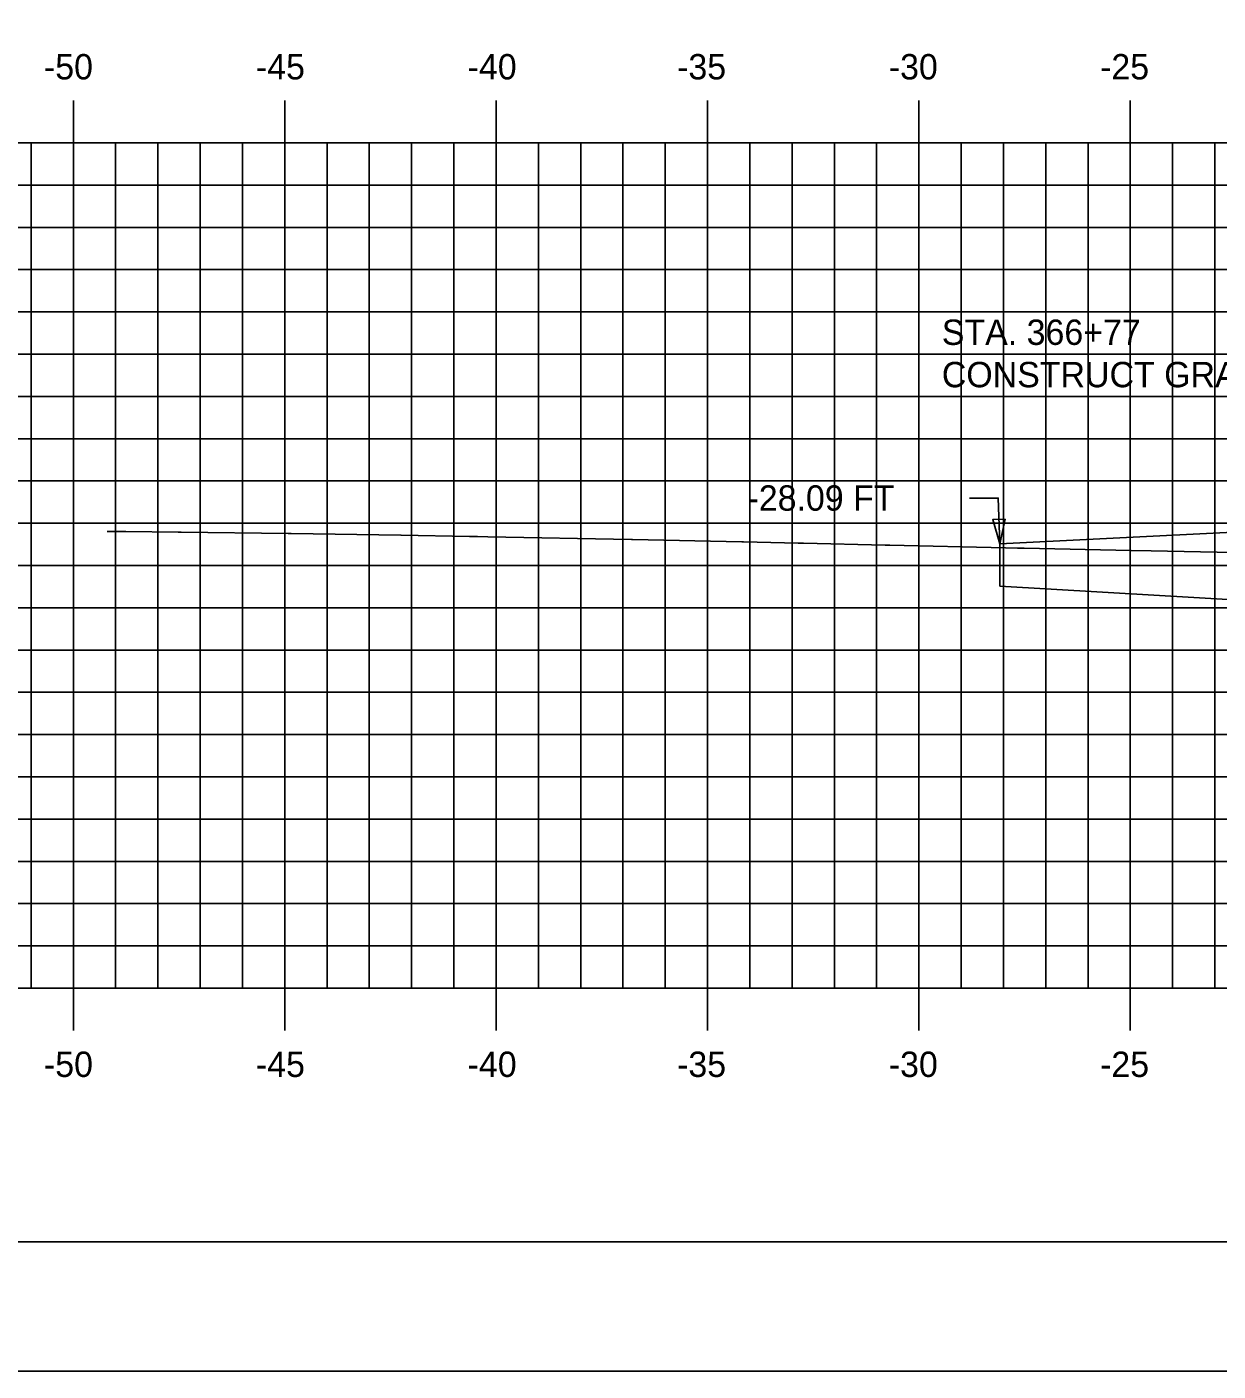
# Model space of a CAD drawing. Extents: x 1147633 to 1147803, y 608981 to 609091.
# Drawn here: x 1147665.35 to 1147693.53, y 608981.28 to 609013.08 of the extents above; entities that cross this region are included whole.
import ezdxf

# ---------------------------------------------------------------- set-up
doc = ezdxf.new("R2010")
doc.units = 0
for name, color, linetype in [('ANNOTATION', 7, 'Continuous'), ('BORDER', 7, 'Continuous'), ('D_Roadway_SubGrade', 7, 'Continuous'), ('D_Text_Standard', 7, 'Continuous'), ('H_V ANNOTATION', 7, 'Continuous'), ('MAJOR', 7, 'Continuous'), ('MINOR', 7, 'Continuous'), ('PLOT BOUNDARY', 7, 'Continuous'), ('S_Roadway_Centerline', 7, 'Continuous')]:
    doc.layers.add(name, color=color, linetype=linetype)

msp = doc.modelspace()

# ---------------------------------------------------------------- linework, layer by layer
msp.add_lwpolyline([(1147688.367, 609000.844), (1147688.37, 609000.845), (1147701.454, 609001.499), (1147701.455, 609001.499), (1147705.454, 609001.659), (1147705.457, 609001.659), (1147716.454, 609001.879), (1147716.457, 609001.879), (1147727.454, 609001.659), (1147727.455, 609001.659), (1147731.454, 609001.499), (1147731.456, 609001.498), (1147739.178, 608998.924), (1147742.178, 608997.924), (1147742.807, 608998.239), (1147744.057, 608998.789), (1147745.307, 608999.188), (1147746.557, 608999.438), (1147747.807, 608999.537)])
at = {"layer": 'BORDER'}
msp.add_lwpolyline([(1147641.454, 608984.335), (1147801.454, 608984.335), (1147801.454, 609089.335), (1147641.454, 609089.335)], close=True, dxfattribs=at)
at = {"layer": 'D_Roadway_SubGrade'}
msp.add_lwpolyline([(1147688.367, 608999.844), (1147701.454, 608999.079), (1147705.454, 608999.159), (1147705.454, 609001.242), (1147705.454, 609001.409), (1147701.454, 609001.249), (1147701.454, 609001.499), (1147688.367, 609000.844)], close=True, dxfattribs=at)
at = {"layer": 'D_Text_Standard'}
msp.add_lwpolyline([(1147688.367, 609000.844), (1147688.331, 609001.932), (1147687.651, 609001.932)], dxfattribs=at)
msp.add_lwpolyline([(1147688.367, 609000.844), (1147688.202, 609001.421), (1147688.493, 609001.431)], close=True, dxfattribs=at)
at = {"layer": 'MAJOR'}
for p, q in [((1147666.454, 609011.337), (1147666.454, 609010.335)), ((1147671.454, 609011.337), (1147671.454, 609010.335)), ((1147676.454, 609011.337), (1147676.454, 609010.335)), ((1147681.454, 609011.337), (1147681.454, 609010.335)), ((1147686.454, 609011.337), (1147686.454, 609010.335)), ((1147691.454, 609011.337), (1147691.454, 609010.335)), ((1147646.454, 609010.335), (1147786.454, 609010.335)), ((1147646.454, 609010.335), (1147786.454, 609010.335)), ((1147666.454, 608990.335), (1147666.454, 609010.335)), ((1147671.454, 608990.335), (1147671.454, 609010.335)), ((1147676.454, 608990.335), (1147676.454, 609010.335)), ((1147681.454, 608990.335), (1147681.454, 609010.335)), ((1147686.454, 608990.335), (1147686.454, 609010.335)), ((1147691.454, 608990.335), (1147691.454, 609010.335)), ((1147646.454, 609005.335), (1147786.454, 609005.335)), ((1147646.454, 609000.335), (1147786.454, 609000.335)), ((1147646.454, 608995.335), (1147786.454, 608995.335)), ((1147646.454, 608990.335), (1147786.454, 608990.335)), ((1147646.454, 608990.335), (1147786.454, 608990.335)), ((1147666.454, 608989.333), (1147666.454, 608990.335)), ((1147671.454, 608989.333), (1147671.454, 608990.335)), ((1147676.454, 608989.333), (1147676.454, 608990.335)), ((1147681.454, 608989.333), (1147681.454, 608990.335)), ((1147686.454, 608989.333), (1147686.454, 608990.335)), ((1147691.454, 608989.333), (1147691.454, 608990.335))]:
    msp.add_line(p, q, dxfattribs=at)
at = {"layer": 'MINOR'}
for p, q in [((1147665.454, 608990.335), (1147665.454, 609010.335)), ((1147667.454, 608990.335), (1147667.454, 609010.335)), ((1147668.454, 608990.335), (1147668.454, 609010.335)), ((1147669.454, 608990.335), (1147669.454, 609010.335)), ((1147670.454, 608990.335), (1147670.454, 609010.335)), ((1147672.454, 608990.335), (1147672.454, 609010.335)), ((1147673.454, 608990.335), (1147673.454, 609010.335)), ((1147674.454, 608990.335), (1147674.454, 609010.335)), ((1147675.454, 608990.335), (1147675.454, 609010.335)), ((1147677.454, 608990.335), (1147677.454, 609010.335)), ((1147678.454, 608990.335), (1147678.454, 609010.335)), ((1147679.454, 608990.335), (1147679.454, 609010.335)), ((1147680.454, 608990.335), (1147680.454, 609010.335)), ((1147682.454, 608990.335), (1147682.454, 609010.335)), ((1147683.454, 608990.335), (1147683.454, 609010.335)), ((1147684.454, 608990.335), (1147684.454, 609010.335)), ((1147685.454, 608990.335), (1147685.454, 609010.335)), ((1147687.454, 608990.335), (1147687.454, 609010.335)), ((1147688.454, 608990.335), (1147688.454, 609010.335)), ((1147689.454, 608990.335), (1147689.454, 609010.335)), ((1147690.454, 608990.335), (1147690.454, 609010.335)), ((1147692.454, 608990.335), (1147692.454, 609010.335)), ((1147693.454, 608990.335), (1147693.454, 609010.335)), ((1147646.454, 609009.335), (1147786.454, 609009.335)), ((1147646.454, 609008.335), (1147786.454, 609008.335)), ((1147646.454, 609007.335), (1147786.454, 609007.335)), ((1147646.454, 609006.335), (1147786.454, 609006.335)), ((1147646.454, 609004.335), (1147786.454, 609004.335)), ((1147646.454, 609003.335), (1147786.454, 609003.335)), ((1147646.454, 609002.335), (1147786.454, 609002.335)), ((1147646.454, 609001.335), (1147786.454, 609001.335)), ((1147646.454, 608999.335), (1147786.454, 608999.335)), ((1147646.454, 608998.335), (1147786.454, 608998.335)), ((1147646.454, 608997.335), (1147786.454, 608997.335)), ((1147646.454, 608996.335), (1147786.454, 608996.335)), ((1147646.454, 608994.335), (1147786.454, 608994.335)), ((1147646.454, 608993.335), (1147786.454, 608993.335)), ((1147646.454, 608992.335), (1147786.454, 608992.335)), ((1147646.454, 608991.335), (1147786.454, 608991.335))]:
    msp.add_line(p, q, dxfattribs=at)
at = {"layer": 'PLOT BOUNDARY'}
msp.add_lwpolyline([(1147633.361, 608981.276), (1147803.361, 608981.276), (1147803.361, 609091.276), (1147633.361, 609091.276)], close=True, dxfattribs=at)
at = {"layer": 'S_Roadway_Centerline'}
msp.add_lwpolyline([(1147667.251, 609001.137), (1147667.309, 609001.138), (1147667.345, 609001.138), (1147667.409, 609001.139), (1147667.532, 609001.14), (1147667.696, 609001.14), (1147668.934, 609001.124), (1147669.006, 609001.124), (1147671.537, 609001.09), (1147671.608, 609001.089), (1147674.199, 609001.051), (1147674.207, 609001.051), (1147675.824, 609001.024), (1147675.98, 609001.022), (1147676.011, 609001.021), (1147676.255, 609001.017), (1147679.656, 609000.954), (1147679.676, 609000.953), (1147682.269, 609000.898), (1147682.308, 609000.897), (1147683.597, 609000.867), (1147683.725, 609000.864), (1147685.66, 609000.819), (1147685.769, 609000.816), (1147688.501, 609000.753), (1147688.783, 609000.747), (1147688.945, 609000.743), (1147691.472, 609000.688), (1147691.948, 609000.679), (1147693.116, 609000.656), (1147694.291, 609000.636)], dxfattribs=at)

# ---------------------------------------------------------------- texts
at = {"layer": 'ANNOTATION'}
for s, p in [('STA. 366+77', (1147686.996, 609005.554)), ('CONSTRUCT GRAVEL ENTRANCE', (1147686.996, 609004.552))]:
    msp.add_text(s, height=0.6, dxfattribs=at).set_placement(p)
at = {"layer": 'D_Text_Standard'}
msp.add_text('-28.09 FT', height=0.6, dxfattribs=at).set_placement((1147682.4, 609001.632))
at = {"layer": 'H_V ANNOTATION'}
for s, p in [('-50', (1147665.758, 609011.835)), ('-45', (1147670.772, 609011.835)), ('-40', (1147675.78, 609011.835)), ('-35', (1147680.734, 609011.835)), ('-30', (1147685.742, 609011.835)), ('-25', (1147690.739, 609011.835)), ('-50', (1147665.758, 608988.235)), ('-45', (1147670.772, 608988.235)), ('-40', (1147675.78, 608988.235)), ('-35', (1147680.734, 608988.235)), ('-30', (1147685.742, 608988.235)), ('-25', (1147690.739, 608988.235))]:
    msp.add_text(s, height=0.6, dxfattribs=at).set_placement(p)

doc.saveas('drawing.dxf')
